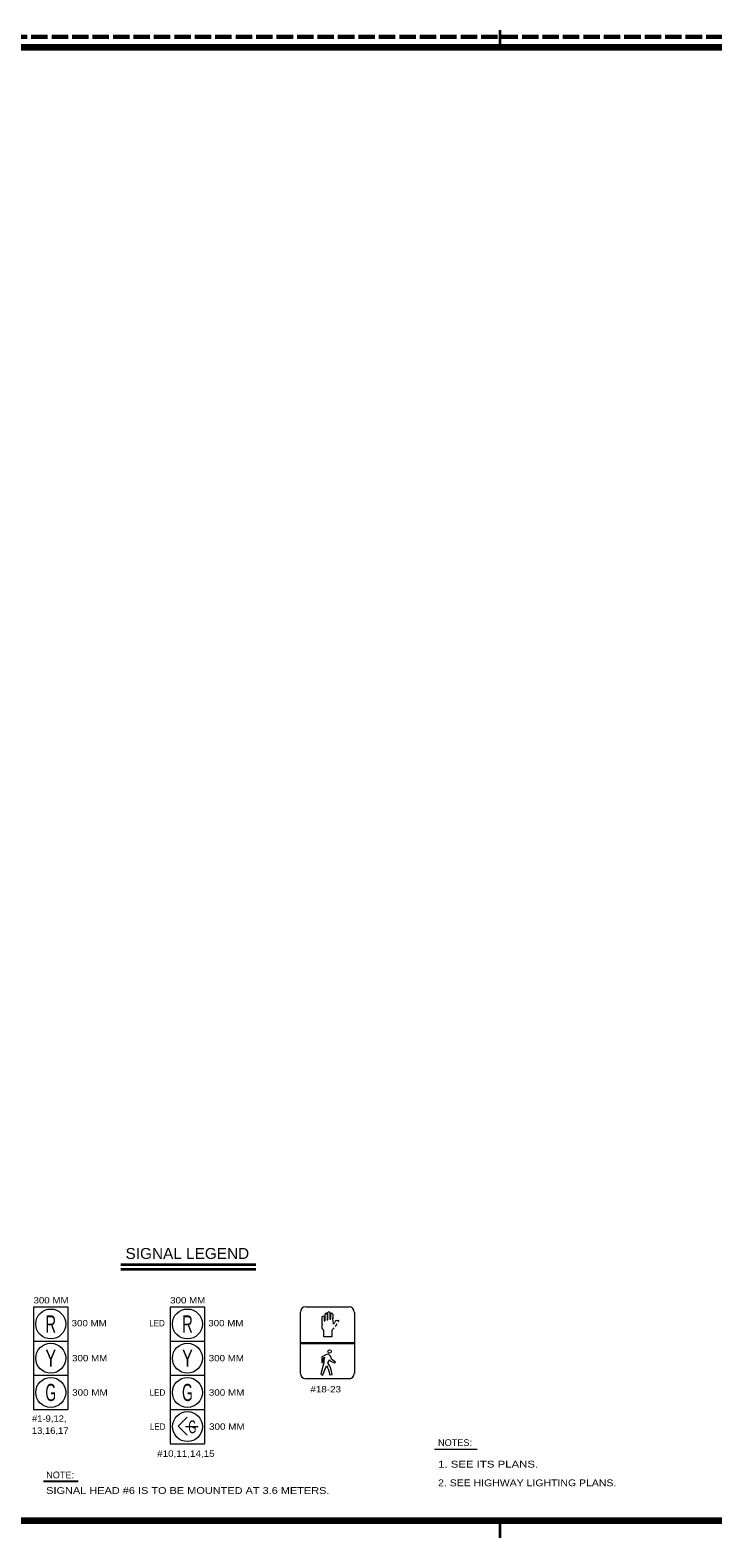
# Model space of a CAD drawing. Extents: x 168203 to 169863, y 223196 to 223870.
# Drawn here: x 169193.4 to 169268.5, y 223534.3 to 223700.1 of the extents above; entities that cross this region are included whole.
import ezdxf
from ezdxf.enums import TextEntityAlignment as Align

# ---------------------------------------------------------------- set-up
doc = ezdxf.new("R2010")
doc.units = 0
doc.header["$LTSCALE"] = 0.3
doc.linetypes.add('LONG_DASHED', pattern=[7.5, 6, -1.5])
for name, color, linetype, lineweight in [('1', 7, 'Continuous', 13), ('10', 7, 'Continuous', 13), ('9', 7, 'Continuous', 13)]:
    doc.layers.add(name, color=color, linetype=linetype, lineweight=lineweight)

msp = doc.modelspace()

# ---------------------------------------------------------------- linework, layer by layer
at = {"layer": '1', "linetype": 'LONG_DASHED', "lineweight": 60}
msp.add_line((169364.0333, 223699.3889), (169095.8093, 223699.3889), dxfattribs=at)
at = {"layer": '1', "lineweight": 35}
for p, q in [((169245.0333, 223700.1389), (169245.0333, 223698.2489)), ((169245.0333, 223536.2489), (169245.0333, 223534.3289))]:
    msp.add_line(p, q, dxfattribs=at)
at = {"layer": '1', "lineweight": 158}
msp.add_lwpolyline([(169361.2833, 223536.2489), (169361.2833, 223698.2489), (169128.7833, 223698.2489), (169128.7833, 223536.2489)], close=True, dxfattribs=at)
at = {"layer": '10', "lineweight": 35}
for p, q in [((169203.3318, 223564.3929), (169218.1946, 223564.3929)), ((169203.3318, 223563.8836), (169218.1946, 223563.8836))]:
    msp.add_line(p, q, dxfattribs=at)
at = {"layer": '10'}
for p, q in [((169193.7447, 223559.7293), (169193.7447, 223548.4431)), ((169193.7447, 223559.7293), (169197.5037, 223559.7293)), ((169197.5037, 223559.7293), (169197.5037, 223552.2022)), ((169208.7807, 223559.7293), (169208.7807, 223548.4431)), ((169208.7807, 223559.7293), (169212.5397, 223559.7293)), ((169212.5397, 223559.7293), (169212.5397, 223552.2022)), ((169223.1029, 223552.401), (169223.1029, 223559.1419)), ((169223.6902, 223559.7293), (169228.4613, 223559.7293)), ((169225.4975, 223557.8227), (169225.4975, 223558.6269)), ((169225.7143, 223558.6269), (169225.7143, 223558.2293)), ((169225.8047, 223558.2293), (169225.8047, 223558.9431)), ((169226.0306, 223558.9431), (169226.0306, 223558.3196)), ((169226.13, 223558.3196), (169226.13, 223559.0968)), ((169226.3378, 223559.0968), (169226.3378, 223558.401)), ((169226.4372, 223558.401), (169226.4372, 223558.9431)), ((169226.6541, 223558.9431), (169226.6541, 223558.401)), ((169229.0396, 223559.1419), (169229.0396, 223552.401)), ((169226.5637, 223557.1178), (169226.5637, 223556.4221)), ((169226.7083, 223557.9221), (169226.7083, 223557.8407)), ((169226.7625, 223557.8769), (169226.8709, 223557.9943)), ((169227.0968, 223557.8588), (169226.9252, 223557.5516)), ((169193.7447, 223555.9703), (169197.5037, 223555.9703)), ((169208.7807, 223555.9703), (169212.5397, 223555.9703)), ((169223.1029, 223555.8257), (169229.0396, 223555.8257)), ((169223.1029, 223555.7172), (169229.0396, 223555.7172)), ((169226.3017, 223553.2775), (169226.13, 223553.5666)), ((169226.2836, 223553.9371), (169226.383, 223553.8016)), ((169193.7537, 223552.2022), (169197.5037, 223552.2022)), ((169197.5128, 223552.2022), (169197.5037, 223552.2022)), ((169197.5128, 223552.2022), (169197.5128, 223548.4431)), ((169208.7897, 223552.2022), (169212.5397, 223552.2022)), ((169212.5488, 223552.2022), (169212.5397, 223552.2022)), ((169212.5488, 223552.2022), (169212.5488, 223548.4431)), ((169228.4613, 223551.8227), (169223.6902, 223551.8227)), ((169193.7447, 223548.4431), (169197.5128, 223548.4431)), ((169208.7807, 223548.4431), (169212.5488, 223548.4431)), ((169208.7807, 223548.4431), (169208.7807, 223544.675)), ((169208.7807, 223548.4431), (169212.5488, 223548.4431)), ((169212.5488, 223548.4431), (169212.5488, 223544.675)), ((169209.6391, 223546.5997), (169210.6331, 223547.5937)), ((169209.6391, 223546.5997), (169210.6331, 223545.6057)), ((169210.4524, 223546.5816), (169211.862, 223546.5816)), ((169208.7807, 223544.675), (169212.5488, 223544.675))]:
    msp.add_line(p, q, dxfattribs=at)
at = {"layer": '10', "lineweight": 25}
msp.add_line((169194.823, 223540.5509), (169198.6485, 223540.5509), dxfattribs=at)
at = {"layer": '10'}
for points in [[(169226.5637, 223556.4221), (169225.6601, 223556.4221), (169225.6601, 223557.1178)], [(169226.8077, 223557.407), (169226.6631, 223557.2805), (169226.5637, 223557.163)], [(169226.9161, 223558.0937), (169227.0246, 223558.2293), (169227.2143, 223558.2654), (169227.2776, 223558.2383), (169227.2776, 223558.1389), (169227.2143, 223558.0937)], [(169225.6782, 223553.5666), (169225.3619, 223552.3648), (169225.5246, 223552.1931), (169225.9673, 223553.2323), (169226.0667, 223553.0968)], [(169226.0306, 223554.5335), (169225.4703, 223554.2443), (169225.4432, 223553.5757), (169225.5426, 223553.6209)], [(169226.4282, 223553.7654), (169226.8529, 223553.5666), (169226.9432, 223553.666), (169226.5095, 223553.9913)], [(169226.1571, 223552.916), (169226.3378, 223552.2383), (169226.5818, 223552.3016), (169226.4372, 223552.9431)]]:
    msp.add_lwpolyline(points, dxfattribs=at)
for centre, radius in [((169195.6289, 223557.8485), 1.6471), ((169210.6649, 223557.8485), 1.6471), ((169195.6289, 223554.0835), 1.6471), ((169210.6649, 223554.0835), 1.6471), ((169226.3095, 223554.8178), 0.1908), ((169195.6289, 223550.3186), 1.6471), ((169210.6649, 223550.3186), 1.6471), ((169210.6731, 223546.5606), 1.6471)]:
    msp.add_circle(centre, radius, dxfattribs=at)
for centre, radius, start, end in [((169223.6813, 223559.1544), 0.5814, 90, 180), ((169229.4185, 223558.4735), 2.7738, 178.64886, 191.22265), ((169228.449, 223559.1544), 0.5814, 0, 90), ((169226.0963, 223557.5957), 0.6422, 159.26718, 226.28376), ((169228.7409, 223553.4286), 3.1988, 166.68273, 176.69799), ((169225.7099, 223554.4911), 0.3359, 255.91002, 284.08998), ((169226.5191, 223553.7234), 0.8512, 148.71844, 190.67186), ((169225.9608, 223554.0127), 0.5396, 358.84706, 81.88202), ((169224.6705, 223554.4123), 1.6775, 329.69374, 343.90908), ((169226.4651, 223553.8696), 0.109, 213.69681, 244.80584), ((169223.6813, 223552.4098), 0.5814, 180, 270), ((169225.6222, 223552.7742), 0.5451, 15.94342, 36.86685), ((169225.3689, 223552.708), 1.0902, 13.24116, 31.96069), ((169228.449, 223552.4098), 0.5814, 270, 0)]:
    msp.add_arc(centre, radius, start, end, dxfattribs=at)
for centre, major_axis, ratio, start_param, end_param in [((169225.6032, 223558.6252), (0.1076, 0), 0.826811, 0, 3.14159265), ((169225.9148, 223558.9428), (0.1076, 0), 0.826811, 0, 3.14159265), ((169226.0706, 223558.3277), (0.0482, 0), 0.809427, 3.14159265, 6.28318531), ((169226.2264, 223559.0996), (0.1076, 0), 0.826811, 0, 3.14159265), ((169226.3822, 223558.4081), (0.0482, 0), 0.809427, 3.14159265, 6.28318531), ((169226.538, 223558.9428), (0.1076, 0), 0.826811, 0, 3.14159265), ((169225.759, 223558.2312), (0.0482, 0), 0.809427, 3.14159265, 6.28318531)]:
    msp.add_ellipse(centre, major_axis=major_axis, ratio=ratio, start_param=start_param, end_param=end_param, dxfattribs=at)
at = {"layer": '9'}
msp.add_line((169237.8444, 223544.0793), (169242.5323, 223544.0793), dxfattribs=at)

# ---------------------------------------------------------------- texts
at = {"layer": '10'}
for s, height, width, p in [('SIGNAL LEGEND', 1.202, 1.05, (169210.6602, 223565.0021)), ('R', 1.88, 0.65, (169195.6314, 223556.91)), ('R', 1.88, 0.65, (169210.6674, 223556.91)), ('Y', 1.88, 0.7, (169195.635, 223553.1419)), ('Y', 1.88, 0.7, (169210.671, 223553.1419)), ('G', 1.889, 0.6, (169195.6314, 223549.3739)), ('G', 1.889, 0.6, (169210.6674, 223549.3739)), ('G', 1.41, 0.6, (169211.2081, 223545.8316))]:
    msp.add_text(s, height=height, dxfattribs=dict(at, width=width)).set_placement(p, align=Align.CENTER)
for s, height, width, p in [('300 MM', 0.6958, 1.15, (169193.7315, 223560.1088)), ('300 MM', 0.6958, 1.15, (169208.7675, 223560.1088)), ('300 MM', 0.6958, 1.15, (169197.9284, 223557.5968)), ('LED', 0.6958, 0.95, (169206.4602, 223557.5968)), ('300 MM', 0.6958, 1.15, (169212.9644, 223557.5968)), ('300 MM', 0.6958, 1.15, (169197.9827, 223553.7474)), ('300 MM', 0.6958, 1.15, (169213.0187, 223553.7474)), ('300 MM', 0.7048, 1.15, (169197.9827, 223549.9612)), ('LED', 0.6958, 0.95, (169206.5145, 223549.9657)), ('300 MM', 0.7048, 1.15, (169213.0187, 223549.9612)), ('#18-23', 0.7048, 1.15, (169224.1934, 223550.3237)), ('#1-9,12,', 0.7048, 1.1, (169193.5667, 223547.094)), ('LED', 0.6958, 0.95, (169206.5416, 223546.2156)), ('300 MM', 0.7048, 1.15, (169213.0458, 223546.2111)), ('13,16,17', 0.7048, 1.1, (169193.5536, 223545.7658)), ('#10,11,14,15', 0.7048, 1.15, (169207.3342, 223543.2369)), ('SIGNAL HEAD #6 IS TO BE MOUNTED AT 3.6 METERS.', 0.75, 1.2, (169195.1273, 223539.1595))]:
    msp.add_text(s, height=height, dxfattribs=dict(at, width=width)).set_placement(p)
msp.add_text('NOTE:', height=0.75, dxfattribs=at).set_placement((169196.6601, 223540.8671), align=Align.CENTER)
at = {"layer": '9'}
msp.add_text('NOTES:', height=0.75, dxfattribs=at).set_placement((169238.2432, 223544.423))
for s, width, p in [('1. SEE ITS PLANS.', 1.25, (169238.2432, 223542.0569)), ('2. SEE HIGHWAY LIGHTING PLANS.', 1.15, (169238.2432, 223540.003))]:
    msp.add_text(s, height=0.75, dxfattribs=dict(at, width=width)).set_placement(p)

doc.saveas('drawing.dxf')
